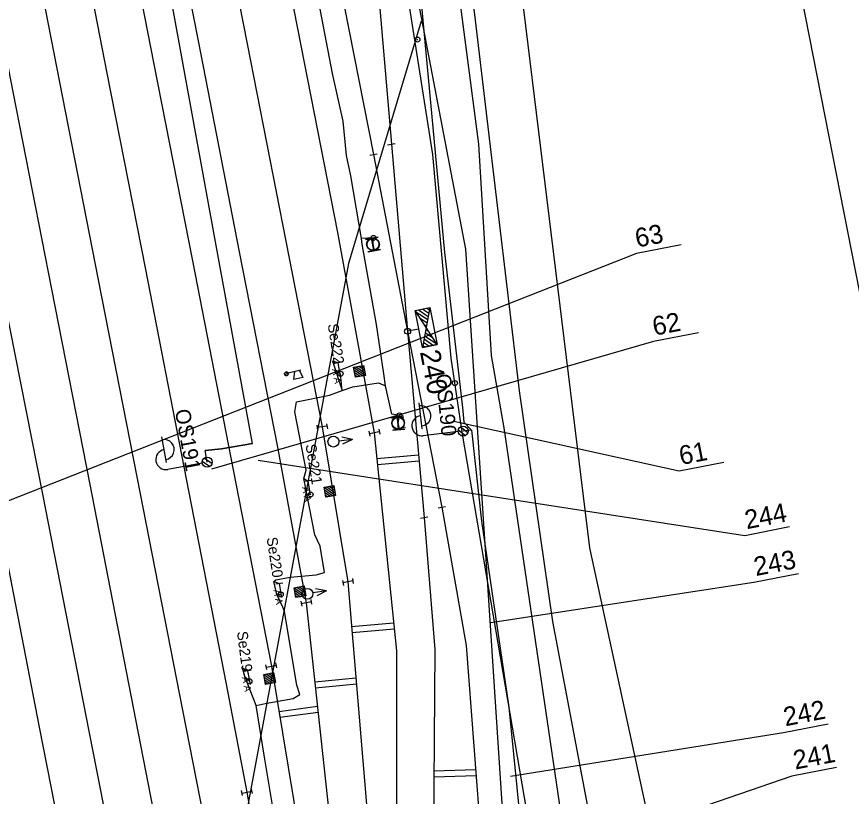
# Model space of a CAD drawing. Extents: x -545846 to -545044, y -1122650 to -1119108.
# Drawn here: x -545438.4 to -545355.4, y -1120179.3 to -1120101.7 of the extents above; entities that cross this region are included whole.
import ezdxf

# ---------------------------------------------------------------- set-up
doc = ezdxf.new("R2010")
doc.units = 0
for name, color, linetype in [('osvětlené plochy-hodnota-obrys', 7, 'Continuous'), ('so180602', 7, 'Continuous'), ('Vrstva 1', 7, 'Continuous'), ('Vrstva 10', 7, 'Continuous'), ('Vrstva 2', 7, 'Continuous'), ('Vrstva 25', 7, 'Continuous'), ('Vrstva 26', 7, 'Continuous'), ('Vrstva 27', 7, 'Continuous'), ('Vrstva 28 - zabzar', 7, 'Continuous'), ('Vrstva 3', 7, 'Continuous'), ('Vrstva 3 - Lisy - Pocitaci body', 7, 'Continuous'), ('Vrstva 33', 7, 'Continuous'), ('Vrstva 35', 7, 'Continuous'), ('Vrstva 50', 7, 'Continuous'), ('Vrstva 51', 7, 'Continuous'), ('Vrstva 6 - Navesti', 7, 'Continuous'), ('Vrstva 62', 7, 'Continuous'), ('Vrstva 63', 7, 'Continuous'), ('Vrstva 7', 7, 'Continuous')]:
    doc.layers.add(name, color=color, linetype=linetype)

msp = doc.modelspace()

# ---------------------------------------------------------------- linework, layer by layer
at = {"layer": 'osvětlené plochy-hodnota-obrys'}
for points in [[(-545520.965, -1119506.473), (-545505.641, -1119546.718), (-545397.928, -1120102.854)], [(-545398.15, -1120102.163), (-545405.365, -1120126.289), (-545451.846, -1120376.212), (-545451.085, -1120446.349), (-545447.102, -1120529.01)], [(-545397.928, -1120102.854), (-545393.734, -1120124.857), (-545389.026, -1120196.694), (-545397.237, -1120293.846), (-545425.658, -1120413.558)]]:
    msp.add_lwpolyline(points, dxfattribs=at)
at = {"layer": 'Vrstva 1'}
for points in [[(-545406.638, -1120070.213), (-545405.761, -1120074.712), (-545403.865, -1120085.82), (-545402.244, -1120100.926), (-545401.108, -1120114.416)], [(-545411.521, -1120071.164), (-545410.602, -1120075.884), (-545405.788, -1120100.651), (-545402.889, -1120115.448)], [(-545416.468, -1120072.127), (-545415.477, -1120077.238), (-545410.442, -1120102.898), (-545406.476, -1120123.181), (-545402.803, -1120143.109), (-545400.596, -1120164.815), (-545400.596, -1120181.651), (-545401.294, -1120192.943)], [(-545421.563, -1120073.119), (-545420.496, -1120078.625), (-545415.445, -1120104.449), (-545411.604, -1120124.066), (-545408, -1120142.528), (-545405.428, -1120157.949)], [(-545426.2, -1120074.022), (-545425.112, -1120079.647), (-545420.052, -1120105.492), (-545416.231, -1120125.122), (-545412.44, -1120144.547), (-545409.571, -1120160.021), (-545407.191, -1120182.024), (-545406.89, -1120192.899), (-545406.905, -1120196.005)], [(-545430.866, -1120074.93), (-545429.748, -1120080.704), (-545424.708, -1120106.469), (-545420.893, -1120126.013), (-545417.075, -1120145.62), (-545413.032, -1120166.33), (-545410.27, -1120183.003), (-545408.743, -1120196.073)], [(-545435.525, -1120075.838), (-545434.405, -1120081.599), (-545429.378, -1120107.352), (-545425.561, -1120126.873), (-545421.731, -1120146.486), (-545417.535, -1120168.115), (-545415.459, -1120178.849), (-545413.975, -1120187.465)], [(-545440.228, -1120076.753), (-545439.131, -1120082.41), (-545434.086, -1120108.231), (-545430.241, -1120127.909), (-545426.423, -1120147.488), (-545422.179, -1120169.181), (-545418.498, -1120187.953)], [(-545444.884, -1120077.66), (-545443.802, -1120083.224), (-545438.728, -1120109.191), (-545434.889, -1120128.845), (-545431.1, -1120148.261), (-545426.768, -1120170.428), (-545421.337, -1120198.338)], [(-545449.597, -1120078.578), (-545448.501, -1120084.223), (-545443.405, -1120110.377), (-545439.586, -1120129.914), (-545435.804, -1120149.227), (-545431.485, -1120171.274), (-545426.936, -1120194.409)], [(-545454.264, -1120079.486), (-545453.059, -1120085.676), (-545448.03, -1120111.514), (-545444.225, -1120130.941), (-545440.471, -1120150.121), (-545436.111, -1120172.393), (-545431.588, -1120195.494)], [(-545401.108, -1120114.416), (-545399.491, -1120133.013), (-545397.857, -1120151.528)], [(-545402.889, -1120115.448), (-545399.491, -1120133.013), (-545396.086, -1120150.507)], [(-545396.086, -1120150.507), (-545393.662, -1120164.267), (-545392.151, -1120184.295), (-545392.126, -1120188.762), (-545392.143, -1120190.552), (-545392.177, -1120191.753)], [(-545397.857, -1120151.528), (-545396.784, -1120164.662), (-545396.964, -1120187.083)], [(-545405.428, -1120157.949), (-545403.439, -1120181.678), (-545403.124, -1120192.894)]]:
    msp.add_lwpolyline(points, dxfattribs=at)
at = {"layer": 'Vrstva 10'}
msp.add_line((-545554.372, -1119108.31), (-545292.195, -1120447.895), dxfattribs=at)
at = {"layer": 'Vrstva 2'}
for p, q in [((-545401.476, -1120114.488), (-545400.74, -1120114.344)), ((-545403.257, -1120115.52), (-545402.521, -1120115.376)), ((-545398.659, -1120131.077), (-545397.492, -1120131.863)), ((-545398.399, -1120130.89), (-545397.431, -1120131.543)), ((-545397.983, -1120130.809), (-545397.37, -1120131.222)), ((-545397.567, -1120130.728), (-545397.309, -1120130.901)), ((-545398.247, -1120131.717), (-545397.554, -1120132.184)), ((-545398.378, -1120132.801), (-545399.491, -1120133.013)), ((-545397.833, -1120132.357), (-545397.614, -1120132.504)), ((-545397.675, -1120132.823), (-545397.423, -1120132.994)), ((-545397.858, -1120133.785), (-545396.914, -1120134.421)), ((-545397.797, -1120133.465), (-545396.597, -1120134.273)), ((-545397.736, -1120133.144), (-545397.01, -1120133.633)), ((-545397.98, -1120134.426), (-545397.747, -1120134.583)), ((-545397.919, -1120134.106), (-545397.331, -1120134.502)), ((-545396.454, -1120150.579), (-545395.718, -1120150.435)), ((-545398.225, -1120151.599), (-545397.489, -1120151.457))]:
    msp.add_line(p, q, dxfattribs=at)
for points in [[(-545401.108, -1120114.416), (-545399.491, -1120133.013), (-545397.857, -1120151.528)], [(-545402.889, -1120115.448), (-545399.491, -1120133.013), (-545396.086, -1120150.507)], [(-545397.265, -1120130.669), (-545397.643, -1120132.653), (-545398.737, -1120130.956), (-545397.265, -1120130.669)], [(-545396.548, -1120134.35), (-545397.643, -1120132.653), (-545398.02, -1120134.637), (-545396.548, -1120134.35)]]:
    msp.add_lwpolyline(points, dxfattribs=at)
msp.add_lwpolyline([(-545397.265, -1120130.669), (-545396.548, -1120134.35), (-545398.02, -1120134.637), (-545398.737, -1120130.956)], close=True, dxfattribs=at)
msp.add_circle((-545399.491, -1120133.013), 0.3, dxfattribs=at)
at = {"layer": 'Vrstva 25'}
for p, q in [((-545398.033, -1120142.71), (-545398.335, -1120140.128)), ((-545394.476, -1120142.999), (-545397.952, -1120143.405)), ((-545393.778, -1120143.399), (-545394.468, -1120142.853)), ((-545393.517, -1120143.128), (-545394.268, -1120142.534)), ((-545423.469, -1120146.07), (-545423.938, -1120143.513)), ((-545419.9, -1120146.127), (-545423.342, -1120146.759)), ((-545419.178, -1120146.481), (-545419.902, -1120145.981)), ((-545418.935, -1120146.193), (-545419.723, -1120145.65))]:
    msp.add_line(p, q, dxfattribs=at)
for centre in [(-545393.979, -1120142.941), (-545393.979, -1120142.941), (-545419.408, -1120146.037), (-545419.408, -1120146.037)]:
    msp.add_circle(centre, 0.5, dxfattribs=at)
for centre, start, end in [((-545398.172, -1120141.417), 275.96408, 97.36923), ((-545398.068, -1120142.412), 96.66666, 276.66666), ((-545423.691, -1120144.789), 279.69384, 101.09899), ((-545423.523, -1120145.775), 100.39642, 280.39642)]:
    msp.add_arc(centre, 1, start, end, dxfattribs=at)
at = {"layer": 'Vrstva 26'}
for points in [[(-545419.408, -1120146.037), (-545419.607, -1120144.864), (-545417.984, -1120144.721), (-545414.909, -1120144.169), (-545418.585, -1120124.133), (-545422.884, -1120100.485), (-545423.39, -1120100.573), (-545423.256, -1120099.117), (-545429.764, -1120065.297), (-545430.312, -1120065.329), (-545430.316, -1120063.627), (-545431.155, -1120058.861), (-545436.816, -1120030.49), (-545441.618, -1120005.901), (-545442.588, -1120002.676)], [(-545398.394, -1120095.592), (-545398.25, -1120099.22), (-545395.83, -1120125.2), (-545394.03, -1120140.6), (-545393.889, -1120142.062), (-545393.145, -1120142.85), (-545393.979, -1120142.941)], [(-545393.145, -1120142.85), (-545392.13, -1120151.91), (-545389.42, -1120170.41), (-545387.82, -1120186.39), (-545387.95, -1120188.71), (-545391.36, -1120189.89), (-545392.84, -1120189.87), (-545394.45, -1120190.07), (-545395.29, -1120199.76), (-545395.06, -1120201.08), (-545395.55, -1120201.04), (-545395.745, -1120200.975)], [(-545414.909, -1120144.169), (-545417.984, -1120144.721), (-545419.607, -1120144.864)]]:
    msp.add_lwpolyline(points, dxfattribs=at)
at = {"layer": 'Vrstva 27'}
for p, q in [((-545402.875, -1120123.755), (-545402.885, -1120123.705)), ((-545406.155, -1120137.265), (-545406.165, -1120137.215)), ((-545400.305, -1120141.365), (-545400.295, -1120141.415)), ((-545409.126, -1120149.275), (-545409.134, -1120149.225)), ((-545412.095, -1120159.215), (-545412.105, -1120159.165)), ((-545415.215, -1120167.855), (-545415.225, -1120167.805))]:
    msp.add_line(p, q, dxfattribs=at)
for centre in [(-545402.88, -1120123.73), (-545406.16, -1120137.24), (-545400.3, -1120141.39), (-545409.13, -1120149.25), (-545412.1, -1120159.19), (-545415.22, -1120167.83)]:
    msp.add_circle(centre, 0.25, dxfattribs=at)
at = {"layer": 'Vrstva 28 - zabzar'}
for p, q in [((-545409.8, -1120147.66), (-545409.38, -1120147.91)), ((-545409.51, -1120149.19), (-545409.13, -1120149.25)), ((-545412.79, -1120157.9), (-545412.24, -1120158.12)), ((-545412.48, -1120159.2), (-545412.1, -1120159.19)), ((-545415.22, -1120167.83), (-545415.69, -1120167.36))]:
    msp.add_line(p, q, dxfattribs=at)
for points in [[(-545400.44, -1120142.19), (-545400.3, -1120141.39), (-545401.05, -1120141.27), (-545401.69, -1120138.45), (-545401.85, -1120137.24), (-545402.58, -1120132.35), (-545404.02, -1120124.35), (-545404.09, -1120123.79), (-545405.15, -1120117.55), (-545405.56, -1120115.55), (-545405.9, -1120112.13), (-545406.95, -1120107.38), (-545409.35, -1120094.87), (-545409.17, -1120093.41), (-545410.42, -1120091.07), (-545410.79, -1120089.43), (-545410.53, -1120088.75), (-545412.47, -1120079.27), (-545412.67, -1120078.51), (-545411.56, -1120078.19), (-545408.79, -1120077.57), (-545407.82, -1120077.37), (-545407.38, -1120081.8), (-545406.84, -1120082)], [(-545402.91, -1120124.39), (-545402.88, -1120123.73), (-545404.09, -1120123.79)], [(-545406.41, -1120136.16), (-545406.96, -1120135.98), (-545406.01, -1120138.92), (-545406.16, -1120137.24)], [(-545414.55, -1120170.22), (-545413.66, -1120170.04), (-545410.88, -1120169.55), (-545410.22, -1120169.14), (-545410.52, -1120168.22), (-545411.74, -1120160.88), (-545411.89, -1120160.47), (-545412.48, -1120159.2), (-545412.79, -1120157.9), (-545412.59, -1120157.75), (-545411.16, -1120157.46), (-545408.59, -1120157.23), (-545407.75, -1120157.02), (-545408.19, -1120154.4), (-545408.72, -1120153.26), (-545409.51, -1120149.19), (-545409.8, -1120147.66), (-545409.57, -1120146.84), (-545410.71, -1120141.04), (-545410.54, -1120140.03), (-545407.24, -1120139.37), (-545406.01, -1120138.92), (-545404.95, -1120138.53), (-545402.39, -1120138.16), (-545401.69, -1120138.45)], [(-545412.44, -1120182.04), (-545412.78, -1120180.96), (-545413.75, -1120175.19), (-545414.55, -1120170.22), (-545415.69, -1120167.36), (-545415.91, -1120166.49), (-545415.39, -1120166.79)]]:
    msp.add_lwpolyline(points, dxfattribs=at)
at = {"layer": 'Vrstva 3'}
for p, q in [((-545403.677, -1120123.868), (-545402.468, -1120123.631)), ((-545402.836, -1120124.959), (-545403.072, -1120123.749)), ((-545403.44, -1120125.077), (-545402.231, -1120124.84)), ((-545407.54, -1120142.211), (-545407.47, -1120142.706)), ((-545401.151, -1120141.625), (-545399.942, -1120141.388)), ((-545400.309, -1120142.715), (-545400.547, -1120141.507)), ((-545408.53, -1120142.35), (-545408.46, -1120142.845)), ((-545407.505, -1120142.458), (-545408.495, -1120142.598)), ((-545403.341, -1120142.959), (-545403.246, -1120143.45)), ((-545402.312, -1120143.014), (-545403.294, -1120143.204)), ((-545402.36, -1120142.768), (-545402.265, -1120143.259)), ((-545400.914, -1120142.834), (-545399.705, -1120142.597)), ((-545404.954, -1120143.794), (-545406.327, -1120143.934)), ((-545404.954, -1120143.794), (-545406.019, -1120143.555)), ((-545404.954, -1120143.794), (-545405.949, -1120144.242)), ((-545405.967, -1120157.799), (-545405.871, -1120158.29)), ((-545404.937, -1120157.853), (-545405.919, -1120158.045)), ((-545404.985, -1120157.608), (-545404.889, -1120158.099)), ((-545407.559, -1120158.817), (-545408.637, -1120158.647)), ((-545407.559, -1120158.817), (-545408.92, -1120159.044)), ((-545407.559, -1120158.817), (-545408.523, -1120159.328)), ((-545410.109, -1120159.871), (-545410.014, -1120160.362)), ((-545409.08, -1120159.926), (-545410.062, -1120160.116)), ((-545409.128, -1120159.68), (-545409.033, -1120160.171)), ((-545413.475, -1120166.671), (-545413.57, -1120166.18)), ((-545413.523, -1120166.425), (-545412.541, -1120166.235)), ((-545412.494, -1120166.48), (-545412.589, -1120165.989)), ((-545415.902, -1120179.19), (-545415.998, -1120178.7)), ((-545414.92, -1120178.998), (-545415.016, -1120178.508)), ((-545415.95, -1120178.945), (-545414.968, -1120178.753))]:
    msp.add_line(p, q, dxfattribs=at)
for centre, radius in [((-545402.955, -1120124.352), 0.616), ((-545400.429, -1120142.109), 0.616), ((-545406.867, -1120143.987), 0.542), ((-545409.456, -1120159.131), 0.542)]:
    msp.add_circle(centre, radius, dxfattribs=at)
at = {"layer": 'Vrstva 3 - Lisy - Pocitaci body'}
for p, q in [((-545403.633, -1120123.904), (-545402.424, -1120123.667)), ((-545402.792, -1120124.995), (-545403.028, -1120123.785)), ((-545403.396, -1120125.113), (-545402.187, -1120124.876)), ((-545404.854, -1120136.6), (-545403.689, -1120137.402)), ((-545404.806, -1120136.86), (-545403.95, -1120137.45)), ((-545404.758, -1120137.121), (-545404.211, -1120137.498)), ((-545404.593, -1120136.552), (-545403.737, -1120137.141)), ((-545404.332, -1120136.503), (-545403.786, -1120136.88)), ((-545404.072, -1120136.455), (-545403.834, -1120136.619)), ((-545404.71, -1120137.382), (-545404.472, -1120137.546)), ((-545401.104, -1120141.626), (-545399.876, -1120141.526)), ((-545400.39, -1120142.804), (-545400.49, -1120141.576)), ((-545401.004, -1120142.854), (-545399.776, -1120142.754)), ((-545407.799, -1120148.521), (-545406.648, -1120149.343)), ((-545407.755, -1120148.783), (-545406.909, -1120149.387)), ((-545407.537, -1120148.478), (-545406.691, -1120149.082)), ((-545407.275, -1120148.434), (-545406.735, -1120148.82)), ((-545407.014, -1120148.39), (-545406.779, -1120148.559)), ((-545407.711, -1120149.045), (-545407.171, -1120149.43)), ((-545407.668, -1120149.306), (-545407.432, -1120149.474)), ((-545410.774, -1120158.521), (-545409.609, -1120159.322)), ((-545410.726, -1120158.781), (-545409.869, -1120159.37)), ((-545410.514, -1120158.472), (-545409.657, -1120159.061)), ((-545410.253, -1120158.424), (-545409.706, -1120158.8)), ((-545409.992, -1120158.376), (-545409.754, -1120158.539)), ((-545410.678, -1120159.042), (-545410.13, -1120159.418)), ((-545410.629, -1120159.303), (-545410.391, -1120159.467)), ((-545413.537, -1120167.1), (-545412.675, -1120167.681)), ((-545413.277, -1120167.049), (-545412.726, -1120167.42)), ((-545413.017, -1120166.998), (-545412.777, -1120167.16)), ((-545413.797, -1120167.151), (-545412.624, -1120167.941)), ((-545413.746, -1120167.411), (-545412.884, -1120167.992)), ((-545413.696, -1120167.672), (-545413.145, -1120168.042)), ((-545413.645, -1120167.932), (-545413.405, -1120168.093))]:
    msp.add_line(p, q, dxfattribs=at)
for points in [[(-545403.871, -1120136.418), (-545403.689, -1120137.402), (-545404.673, -1120137.583), (-545404.854, -1120136.6)], [(-545406.812, -1120148.357), (-545406.648, -1120149.343), (-545407.634, -1120149.508), (-545407.799, -1120148.521)], [(-545409.791, -1120158.338), (-545409.609, -1120159.322), (-545410.592, -1120159.504), (-545410.774, -1120158.521)], [(-545412.816, -1120166.959), (-545412.624, -1120167.941), (-545413.606, -1120168.132), (-545413.797, -1120167.151)]]:
    msp.add_lwpolyline(points, close=True, dxfattribs=at)
for centre in [(-545402.911, -1120124.388), (-545400.441, -1120142.188)]:
    msp.add_circle(centre, 0.616, dxfattribs=at)
at = {"layer": 'Vrstva 33'}
for p, q in [((-545411.617, -1120137.078), (-545411.361, -1120137.265)), ((-545410.118, -1120136.902), (-545411.363, -1120137.199)), ((-545410.806, -1120137.822), (-545410.697, -1120137.04)), ((-545410.252, -1120136.934), (-545409.916, -1120137.61)), ((-545411.718, -1120137.248), (-545411.467, -1120137.431)), ((-545409.916, -1120137.61), (-545410.806, -1120137.822))]:
    msp.add_line(p, q, dxfattribs=at)
for major_axis in [(-0.044, -0.195), (-0.044, -0.196)]:
    msp.add_ellipse((-545411.539, -1120137.253), major_axis=major_axis, ratio=0.897978, dxfattribs=at)
at = {"layer": 'Vrstva 35'}
for points in [[(-545410.54, -1120140.03), (-545407.24, -1120139.37), (-545406.01, -1120138.92), (-545404.95, -1120138.53), (-545402.39, -1120138.16), (-545401.69, -1120138.45)], [(-545412.59, -1120157.75), (-545411.16, -1120157.46), (-545408.59, -1120157.23), (-545407.75, -1120157.02)], [(-545414.55, -1120170.22), (-545413.66, -1120170.04), (-545410.88, -1120169.55), (-545410.22, -1120169.14)]]:
    msp.add_lwpolyline(points, dxfattribs=at)
at = {"layer": 'Vrstva 50'}
for p, q in [((-545398.539, -1120104.007), (-545398.489, -1120104.007)), ((-545394.809, -1120138.171), (-545394.759, -1120138.171))]:
    msp.add_line(p, q, dxfattribs=at)
for centre in [(-545398.514, -1120104.007), (-545394.784, -1120138.171)]:
    msp.add_circle(centre, 0.25, dxfattribs=at)
at = {"layer": 'Vrstva 51'}
for points in [[(-545474.36, -1119688.255), (-545466.579, -1119732.11), (-545462.51, -1119756.655), (-545455.831, -1119789.993), (-545450.917, -1119814.901), (-545443.717, -1119850.687), (-545439.158, -1119879.07), (-545432.576, -1119913.186), (-545426.875, -1119936.671), (-545422.743, -1119962.506), (-545418.335, -1119990.017), (-545411.428, -1120016.49), (-545406.245, -1120044.568), (-545403.533, -1120065.521), (-545401.184, -1120088.868), (-545397.016, -1120115.443), (-545395.196, -1120135.679), (-545394.057, -1120143.256), (-545386.488, -1120187.748)], [(-545470.7, -1119687.746), (-545464.137, -1119731.581), (-545459.972, -1119755.883), (-545452.874, -1119789.329), (-545448.102, -1119814.108), (-545441.139, -1119850.218), (-545435.794, -1119878.29), (-545429.367, -1119912.848), (-545423.033, -1119935.797), (-545419.144, -1119961.66), (-545414.863, -1119988.762), (-545403.007, -1120044.19), (-545400.258, -1120064.288), (-545395.915, -1120087.784), (-545392.445, -1120114.396), (-545391.179, -1120135.428), (-545389.936, -1120142.632), (-545383.231, -1120188.01)]]:
    msp.add_lwpolyline(points, dxfattribs=at)
at = {"layer": 'Vrstva 6 - Navesti'}
for p, q in [((-545406.066, -1120136.097), (-545406.754, -1120136.223)), ((-545406.159, -1120137.523), (-545406.41, -1120136.16)), ((-545409.035, -1120147.852), (-545409.725, -1120147.968)), ((-545409.152, -1120149.277), (-545409.38, -1120147.91)), ((-545411.896, -1120158.056), (-545412.584, -1120158.184)), ((-545411.987, -1120159.483), (-545412.24, -1120158.12)), ((-545415.046, -1120166.723), (-545415.734, -1120166.857)), ((-545415.124, -1120168.15), (-545415.39, -1120166.79))]:
    msp.add_line(p, q, dxfattribs=at)
at = {"layer": 'Vrstva 62'}
for points in [[(-545423.216, -1119917.425), (-545425.626, -1119923.902), (-545421.66, -1119936.357), (-545417.987, -1119968.93), (-545408.636, -1120019.429), (-545402.531, -1120045.967), (-545395.226, -1120081.877), (-545392.76, -1120102.085), (-545388.408, -1120138.929), (-545385.069, -1120161.88), (-545380.677, -1120185.181), (-545377.636, -1120190.956), (-545375.6, -1120199.999)], [(-545371.516, -1120199.999), (-545381.387, -1120154.552), (-545388.984, -1120092.348), (-545395.017, -1120062.684), (-545403.862, -1120025.812), (-545411.302, -1119985.582), (-545417.876, -1119943.114), (-545420.973, -1119925.302), (-545417.81, -1119919.208)]]:
    msp.add_lwpolyline(points, dxfattribs=at)
at = {"layer": 'Vrstva 63'}
for p, q in [((-545372.301, -1120124.418), (-545376.745, -1120125.282)), ((-545376.745, -1120125.282), (-545442.712, -1120151.277)), ((-545370.584, -1120133.188), (-545375.029, -1120134.052)), ((-545375.029, -1120134.052), (-545418.994, -1120146.742)), ((-545372.507, -1120146.938), (-545394.9, -1120141.992)), ((-545365.967, -1120153.347), (-545414.363, -1120145.872)), ((-545368.062, -1120146.074), (-545372.507, -1120146.938)), ((-545361.523, -1120152.483), (-545365.967, -1120153.347)), ((-545361.523, -1120152.483), (-545365.967, -1120153.347)), ((-545361.523, -1120152.483), (-545365.967, -1120153.347)), ((-545360.612, -1120157.139), (-545365.056, -1120158.003)), ((-545360.612, -1120157.139), (-545365.056, -1120158.003)), ((-545360.612, -1120157.139), (-545365.056, -1120158.003)), ((-545365.056, -1120158.003), (-545391.225, -1120162.019)), ((-545357.687, -1120172.082), (-545362.131, -1120172.946)), ((-545357.687, -1120172.082), (-545362.131, -1120172.946)), ((-545357.687, -1120172.082), (-545362.131, -1120172.946)), ((-545362.131, -1120172.946), (-545389.254, -1120177.299)), ((-545356.839, -1120176.413), (-545361.284, -1120177.277)), ((-545356.839, -1120176.413), (-545361.284, -1120177.277)), ((-545356.839, -1120176.413), (-545361.284, -1120177.277)), ((-545361.284, -1120177.277), (-545394.413, -1120188.57))]:
    msp.add_line(p, q, dxfattribs=at)
at = {"layer": 'Vrstva 7'}
for p, q in [((-545402.541, -1120145.683), (-545398.407, -1120145.291)), ((-545402.481, -1120146.28), (-545398.355, -1120145.888)), ((-545405.056, -1120162.391), (-545400.882, -1120162.004)), ((-545405.006, -1120162.989), (-545400.821, -1120162.601)), ((-545404.625, -1120167.532), (-545408.716, -1120167.925)), ((-545404.575, -1120168.13), (-545408.651, -1120168.522)), ((-545412.288, -1120170.821), (-545408.459, -1120170.297)), ((-545412.19, -1120171.413), (-545408.395, -1120170.894)), ((-545396.881, -1120176.732), (-545392.732, -1120176.592)), ((-545396.886, -1120177.332), (-545392.687, -1120177.191))]:
    msp.add_line(p, q, dxfattribs=at)

# ---------------------------------------------------------------- texts
at = {"layer": 'so180602'}
for s, p in [('63', (-545376.684, -1120124.701)), ('62', (-545374.954, -1120133.469)), ('61', (-545372.307, -1120146.33)), ('244', (-545365.778, -1120152.711)), ('243', (-545364.867, -1120157.367)), ('242', (-545361.929, -1120172.307)), ('241', (-545360.956, -1120176.614))]:
    msp.add_text(s, height=1.875, rotation=10.99553, dxfattribs=at).set_placement(p)
at = {"layer": 'Vrstva 2'}
msp.add_text('240', height=2, rotation=281.03148, dxfattribs=at).set_placement((-545398.273, -1120135.059))
at = {"layer": 'Vrstva 25'}
for s, rotation, p in [('OS190', 275.50875, (-545396.701, -1120137.307)), ('OS191', 280.39642, (-545422.638, -1120140.893))]:
    msp.add_text(s, height=1.5, rotation=rotation, dxfattribs=at).set_placement(p)
at = {"layer": 'Vrstva 6 - Navesti'}
for s, height, rotation, p in [('Se222', 1.05, 278.78475, (-545407.436, -1120132.34)), ('  A A ', 0.7, 280.44318, (-545407.098, -1120136.287)), ('Se221', 1.05, 279.09924, (-545409.642, -1120144.314)), ('  A A ', 0.7, 279.46895, (-545410.07, -1120148.025)), ('Se220', 1.05, 278.56197, (-545413.509, -1120153.568)), ('  A A ', 0.7, 280.50381, (-545412.928, -1120158.248)), ('Se219', 1.05, 277.22565, (-545416.457, -1120162.913)), ('  A A ', 0.7, 281.04634, (-545416.077, -1120166.924))]:
    msp.add_text(s, height=height, rotation=rotation, dxfattribs=at).set_placement(p)

doc.saveas('drawing.dxf')
